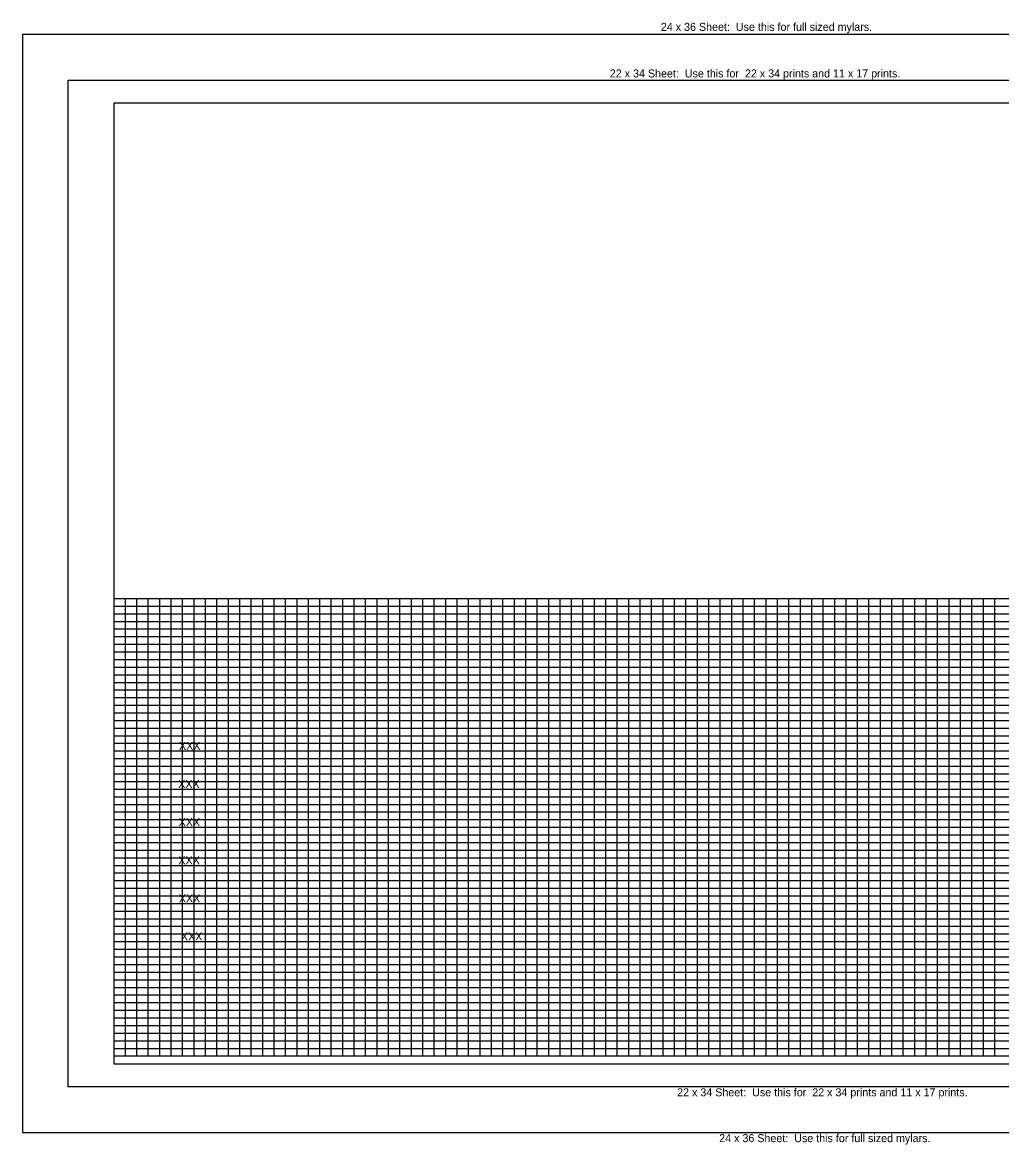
# Model space of a CAD drawing. Extents: x -4115 to -3256, y -1337 to -847.
# Drawn here: x -4115.5 to -3688, y -1337.1 to -846.5 of the extents above; entities that cross this region are included whole.
import ezdxf

# ---------------------------------------------------------------- set-up
doc = ezdxf.new("R2010")
doc.units = 0
for name, color, linetype in [('G_BORDER', 7, 'Continuous'), ('G_GRID_MAJOR', 7, 'Continuous'), ('G_GRID_MINOR', 7, 'Continuous'), ('G_SHEET_EDGE', 7, 'Continuous')]:
    doc.layers.add(name, color=color, linetype=linetype)

msp = doc.modelspace()

# ---------------------------------------------------------------- linework, layer by layer
at = {"layer": 'G_BORDER'}
msp.add_lwpolyline([(-4075.45, -1301.8), (-3425.45, -1301.8), (-3425.45, -881.8), (-4075.45, -881.8)], close=True, dxfattribs=at)
at = {"layer": 'G_GRID_MAJOR'}
for p, q in [((-3540.45, -1098.47), (-4075.45, -1098.47)), ((-4030.45, -1298.47), (-4030.45, -1098.47)), ((-3980.45, -1298.47), (-3980.45, -1098.47)), ((-3930.45, -1298.47), (-3930.45, -1098.47)), ((-3880.45, -1298.47), (-3880.45, -1098.47)), ((-3830.45, -1298.47), (-3830.45, -1098.47)), ((-3780.45, -1298.47), (-3780.45, -1098.47)), ((-3730.45, -1298.47), (-3730.45, -1098.47)), ((-3540.45, -1115.14), (-4075.45, -1115.14)), ((-3540.45, -1131.8), (-4075.45, -1131.8)), ((-3540.45, -1148.47), (-4075.45, -1148.47)), ((-3540.45, -1165.14), (-4075.45, -1165.14)), ((-3540.45, -1181.8), (-4075.45, -1181.8)), ((-3540.45, -1198.47), (-4075.45, -1198.47)), ((-3540.45, -1215.14), (-4075.45, -1215.14)), ((-3540.45, -1231.8), (-4075.45, -1231.8)), ((-3540.45, -1248.47), (-4075.45, -1248.47)), ((-3540.45, -1265.14), (-4075.45, -1265.14)), ((-3540.45, -1281.8), (-4075.45, -1281.8)), ((-3540.45, -1298.47), (-4075.45, -1298.47))]:
    msp.add_line(p, q, dxfattribs=at)
at = {"layer": 'G_GRID_MINOR'}
for p, q in [((-4070.45, -1298.47), (-4070.45, -1098.47)), ((-4065.45, -1298.47), (-4065.45, -1098.47)), ((-4060.45, -1298.47), (-4060.45, -1098.47)), ((-4055.45, -1298.47), (-4055.45, -1098.47)), ((-4050.45, -1298.47), (-4050.45, -1098.47)), ((-4045.45, -1298.47), (-4045.45, -1098.47)), ((-4040.45, -1298.47), (-4040.45, -1098.47)), ((-4035.45, -1298.47), (-4035.45, -1098.47)), ((-4025.45, -1298.47), (-4025.45, -1098.47)), ((-4020.45, -1298.47), (-4020.45, -1098.47)), ((-4015.45, -1298.47), (-4015.45, -1098.47)), ((-4010.45, -1298.47), (-4010.45, -1098.47)), ((-4005.45, -1298.47), (-4005.45, -1098.47)), ((-4000.45, -1298.47), (-4000.45, -1098.47)), ((-3995.45, -1298.47), (-3995.45, -1098.47)), ((-3990.45, -1298.47), (-3990.45, -1098.47)), ((-3985.45, -1298.47), (-3985.45, -1098.47)), ((-3975.45, -1298.47), (-3975.45, -1098.47)), ((-3970.45, -1298.47), (-3970.45, -1098.47)), ((-3965.45, -1298.47), (-3965.45, -1098.47)), ((-3960.45, -1298.47), (-3960.45, -1098.47)), ((-3955.45, -1298.47), (-3955.45, -1098.47)), ((-3950.45, -1298.47), (-3950.45, -1098.47)), ((-3945.45, -1298.47), (-3945.45, -1098.47)), ((-3940.45, -1298.47), (-3940.45, -1098.47)), ((-3935.45, -1298.47), (-3935.45, -1098.47)), ((-3925.45, -1298.47), (-3925.45, -1098.47)), ((-3920.45, -1298.47), (-3920.45, -1098.47)), ((-3915.45, -1298.47), (-3915.45, -1098.47)), ((-3910.45, -1298.47), (-3910.45, -1098.47)), ((-3905.45, -1298.47), (-3905.45, -1098.47)), ((-3900.45, -1298.47), (-3900.45, -1098.47)), ((-3895.45, -1298.47), (-3895.45, -1098.47)), ((-3890.45, -1298.47), (-3890.45, -1098.47)), ((-3885.45, -1298.47), (-3885.45, -1098.47)), ((-3875.45, -1298.47), (-3875.45, -1098.47)), ((-3870.45, -1298.47), (-3870.45, -1098.47)), ((-3865.45, -1298.47), (-3865.45, -1098.47)), ((-3860.45, -1298.47), (-3860.45, -1098.47)), ((-3855.45, -1298.47), (-3855.45, -1098.47)), ((-3850.45, -1298.47), (-3850.45, -1098.47)), ((-3845.45, -1298.47), (-3845.45, -1098.47)), ((-3840.45, -1298.47), (-3840.45, -1098.47)), ((-3835.45, -1298.47), (-3835.45, -1098.47)), ((-3825.45, -1298.47), (-3825.45, -1098.47)), ((-3820.45, -1298.47), (-3820.45, -1098.47)), ((-3815.45, -1298.47), (-3815.45, -1098.47)), ((-3810.45, -1298.47), (-3810.45, -1098.47)), ((-3805.45, -1298.47), (-3805.45, -1098.47)), ((-3800.45, -1298.47), (-3800.45, -1098.47)), ((-3795.45, -1298.47), (-3795.45, -1098.47)), ((-3790.45, -1298.47), (-3790.45, -1098.47)), ((-3785.45, -1298.47), (-3785.45, -1098.47)), ((-3775.45, -1298.47), (-3775.45, -1098.47)), ((-3770.45, -1298.47), (-3770.45, -1098.47)), ((-3765.45, -1298.47), (-3765.45, -1098.47)), ((-3760.45, -1298.47), (-3760.45, -1098.47)), ((-3755.45, -1298.47), (-3755.45, -1098.47)), ((-3750.45, -1298.47), (-3750.45, -1098.47)), ((-3745.45, -1298.47), (-3745.45, -1098.47)), ((-3740.45, -1298.47), (-3740.45, -1098.47)), ((-3735.45, -1298.47), (-3735.45, -1098.47)), ((-3725.45, -1298.47), (-3725.45, -1098.47)), ((-3720.45, -1298.47), (-3720.45, -1098.47)), ((-3715.45, -1298.47), (-3715.45, -1098.47)), ((-3710.45, -1298.47), (-3710.45, -1098.47)), ((-3705.45, -1298.47), (-3705.45, -1098.47)), ((-3700.45, -1298.47), (-3700.45, -1098.47)), ((-3695.45, -1298.47), (-3695.45, -1098.47)), ((-3690.45, -1298.47), (-3690.45, -1098.47)), ((-3540.45, -1101.8), (-4075.45, -1101.8)), ((-3540.45, -1105.14), (-4075.45, -1105.14)), ((-3540.45, -1108.47), (-4075.45, -1108.47)), ((-3540.45, -1111.8), (-4075.45, -1111.8)), ((-3540.45, -1118.47), (-4075.45, -1118.47)), ((-3540.45, -1121.8), (-4075.45, -1121.8)), ((-3540.45, -1125.14), (-4075.45, -1125.14)), ((-3540.45, -1128.47), (-4075.45, -1128.47)), ((-3540.45, -1135.14), (-4075.45, -1135.14)), ((-3540.45, -1138.47), (-4075.45, -1138.47)), ((-3540.45, -1141.8), (-4075.45, -1141.8)), ((-3540.45, -1145.14), (-4075.45, -1145.14)), ((-3540.45, -1151.8), (-4075.45, -1151.8)), ((-3540.45, -1155.14), (-4075.45, -1155.14)), ((-3540.45, -1158.47), (-4075.45, -1158.47)), ((-3540.45, -1161.8), (-4075.45, -1161.8)), ((-3540.45, -1168.47), (-4075.45, -1168.47)), ((-3540.45, -1171.8), (-4075.45, -1171.8)), ((-3540.45, -1175.14), (-4075.45, -1175.14)), ((-3540.45, -1178.47), (-4075.45, -1178.47)), ((-3540.45, -1185.14), (-4075.45, -1185.14)), ((-3540.45, -1188.47), (-4075.45, -1188.47)), ((-3540.45, -1191.8), (-4075.45, -1191.8)), ((-3540.45, -1195.14), (-4075.45, -1195.14)), ((-3540.45, -1201.8), (-4075.45, -1201.8)), ((-3540.45, -1205.14), (-4075.45, -1205.14)), ((-3540.45, -1208.47), (-4075.45, -1208.47)), ((-3540.45, -1211.8), (-4075.45, -1211.8)), ((-3540.45, -1218.47), (-4075.45, -1218.47)), ((-3540.45, -1221.8), (-4075.45, -1221.8)), ((-3540.45, -1225.14), (-4075.45, -1225.14)), ((-3540.45, -1228.47), (-4075.45, -1228.47)), ((-3540.45, -1235.14), (-4075.45, -1235.14)), ((-3540.45, -1238.47), (-4075.45, -1238.47)), ((-3540.45, -1241.8), (-4075.45, -1241.8)), ((-3540.45, -1245.14), (-4075.45, -1245.14)), ((-3540.45, -1251.8), (-4075.45, -1251.8)), ((-3540.45, -1255.14), (-4075.45, -1255.14)), ((-3540.45, -1258.47), (-4075.45, -1258.47)), ((-3540.45, -1261.8), (-4075.45, -1261.8)), ((-3540.45, -1268.47), (-4075.45, -1268.47)), ((-3540.45, -1271.8), (-4075.45, -1271.8)), ((-3540.45, -1275.14), (-4075.45, -1275.14)), ((-3540.45, -1278.47), (-4075.45, -1278.47)), ((-3540.45, -1285.14), (-4075.45, -1285.14)), ((-3540.45, -1288.47), (-4075.45, -1288.47)), ((-3540.45, -1291.8), (-4075.45, -1291.8)), ((-3540.45, -1295.14), (-4075.45, -1295.14))]:
    msp.add_line(p, q, dxfattribs=at)
at = {"layer": 'G_SHEET_EDGE'}
for points in [[(-4115.45, -1331.8), (-3395.45, -1331.8), (-3395.45, -851.8), (-4115.45, -851.8)], [(-4095.45, -871.8), (-3415.45, -871.8), (-3415.45, -1311.8), (-4095.45, -1311.8)]]:
    msp.add_lwpolyline(points, close=True, dxfattribs=at)

# ---------------------------------------------------------------- texts
at = {"layer": 'G_GRID_MAJOR'}
for p in [(-4047.03, -1164.51), (-4047.38, -1181.18), (-4047.17, -1197.84), (-4047.31, -1214.51), (-4047.1, -1231.18), (-4046.17, -1247.84)]:
    msp.add_text('XXX', height=3.5, dxfattribs=at).set_placement(p)
at = {"layer": 'G_SHEET_EDGE'}
for s, p in [('24 x 36 Sheet:  Use this for full sized mylars. ', (-3836.42, -850.2)), ('22 x 34 Sheet:  Use this for  22 x 34 prints and 11 x 17 prints. ', (-3858.73, -870.55)), ('22 x 34 Sheet:  Use this for  22 x 34 prints and 11 x 17 prints. ', (-3829.3, -1315.96)), ('24 x 36 Sheet:  Use this for full sized mylars. ', (-3810.92, -1336))]:
    msp.add_text(s, height=3.5, dxfattribs=at).set_placement(p)

doc.saveas('drawing.dxf')
